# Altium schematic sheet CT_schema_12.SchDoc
size 389 x 385 mm
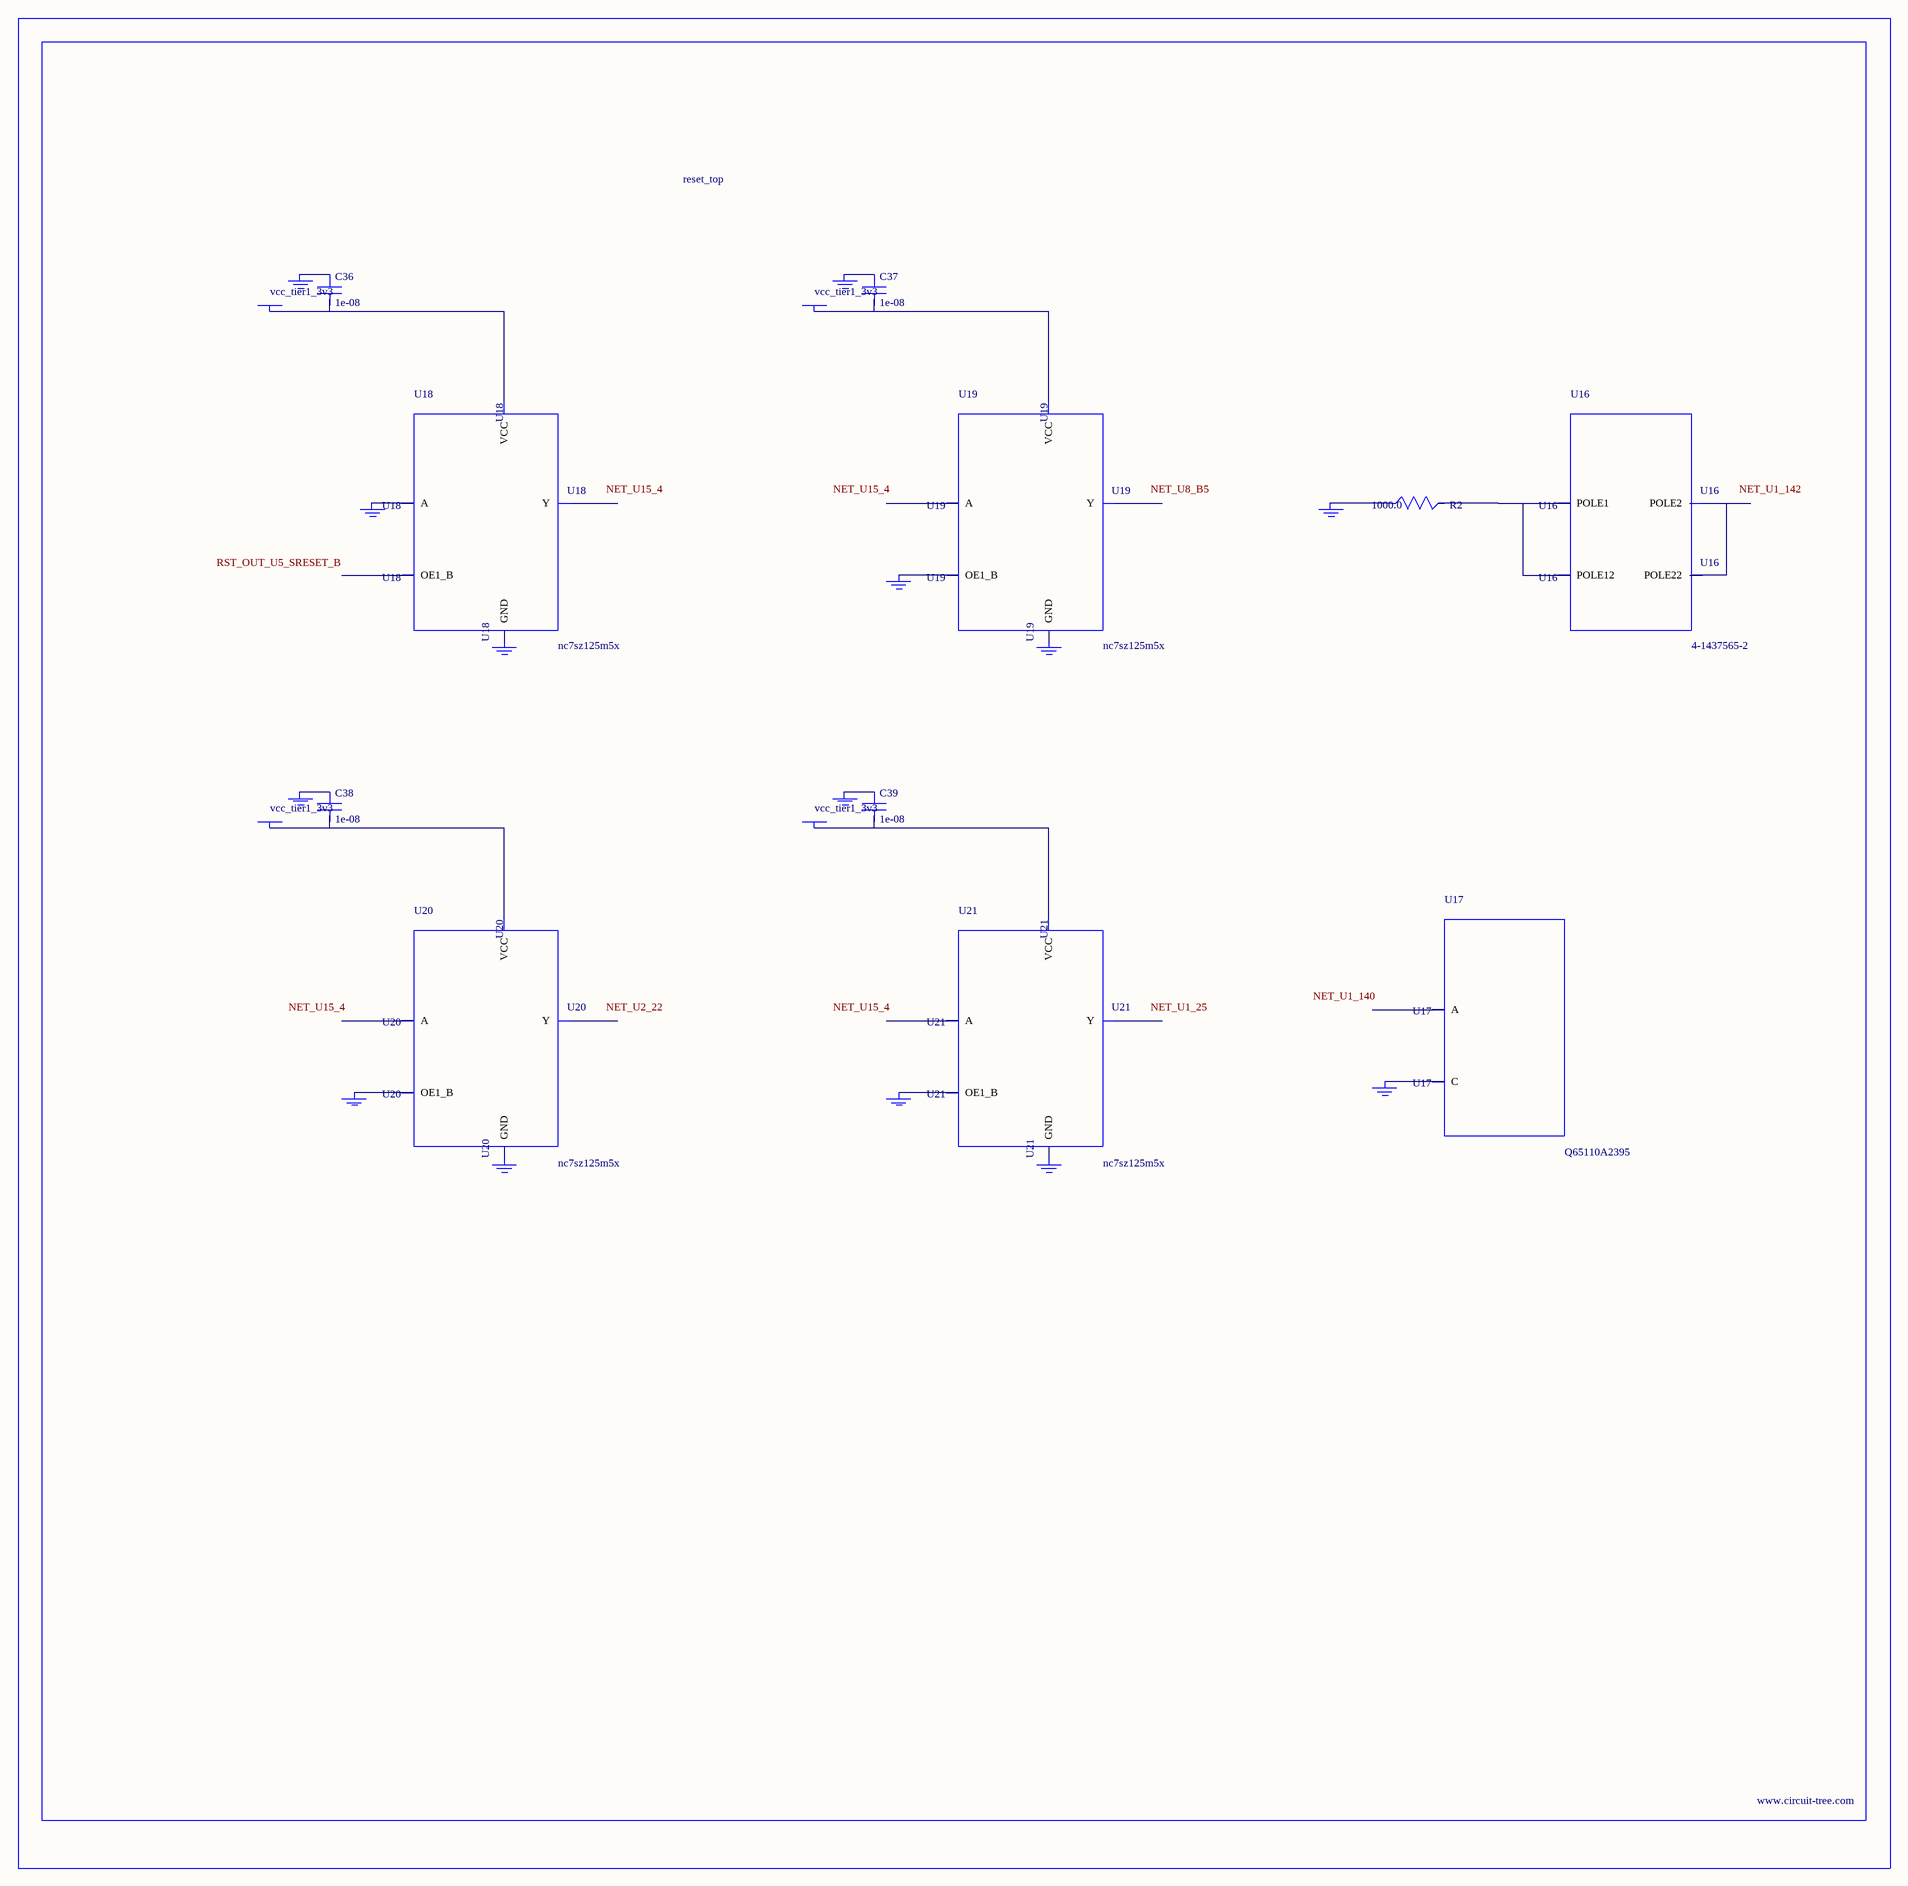
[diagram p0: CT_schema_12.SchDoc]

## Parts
BORDER11  (no value)
C36  1e-08  [C0402]
C37  1e-08  [C0402]
C38  1e-08  [C0402]
C39  1e-08  [C0402]
GND_INSTANCE_11_0  (no value)
GND_INSTANCE_11_1  (no value)
GND_INSTANCE_11_2  (no value)
GND_INSTANCE_11_3  (no value)
GND_INSTANCE_11_4  (no value)
GND_INSTANCE_11_5  (no value)
GND_INSTANCE_11_6  (no value)
GND_INSTANCE_11_7  (no value)
GND_INSTANCE_11_8  (no value)
GND_INSTANCE_11_9  (no value)
GND_INSTANCE_11_10  (no value)
GND_INSTANCE_11_11  (no value)
GND_INSTANCE_11_12  (no value)
GND_INSTANCE_11_13  (no value)
POWER_INSTANCE_11_0  vcc_tier1_3v3
POWER_INSTANCE_11_1  vcc_tier1_3v3
POWER_INSTANCE_11_2  vcc_tier1_3v3
POWER_INSTANCE_11_3  vcc_tier1_3v3
R2  1000.0  [R0603]
U16  4-1437565-2  [SW_4-1437565-2]
U17  Q65110A2395  [LGM67K-G1J2-24-Z]
U18  nc7sz125m5x  [NC7SZ125M5X]
U19  nc7sz125m5x  [NC7SZ125M5X]
U20  nc7sz125m5x  [NC7SZ125M5X]
U21  nc7sz125m5x  [NC7SZ125M5X]

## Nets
NetC36_1: C36.1 GND_INSTANCE_11_2.0(GND)
NetC36_2: C36.2 POWER_INSTANCE_11_0.0(PWR) U18.5(VCC)
NetC37_1: C37.1 GND_INSTANCE_11_5.0(GND)
NetC37_2: C37.2 POWER_INSTANCE_11_1.0(PWR) U19.5(VCC)
NetC38_1: C38.1 GND_INSTANCE_11_8.0(GND)
NetC38_2: C38.2 POWER_INSTANCE_11_2.0(PWR) U20.5(VCC)
NetC39_1: C39.1 GND_INSTANCE_11_11.0(GND)
NetC39_2: C39.2 POWER_INSTANCE_11_3.0(PWR) U21.5(VCC)
NetGND_INSTANCE_11_0_0: GND_INSTANCE_11_0.0(GND) R2.1
NetGND_INSTANCE_11_1_0: GND_INSTANCE_11_1.0(GND) U17.C
NetGND_INSTANCE_11_3_0: GND_INSTANCE_11_3.0(GND) U18.2(A)
NetGND_INSTANCE_11_4_0: GND_INSTANCE_11_4.0(GND) U18.3(GND)
NetGND_INSTANCE_11_6_0: GND_INSTANCE_11_6.0(GND) U19.1(OE1_B)
NetGND_INSTANCE_11_7_0: GND_INSTANCE_11_7.0(GND) U19.3(GND)
NetGND_INSTANCE_11_9_0: GND_INSTANCE_11_9.0(GND) U20.1(OE1_B)
NetGND_INSTANCE_11_10_0: GND_INSTANCE_11_10.0(GND) U20.3(GND)
NetGND_INSTANCE_11_12_0: GND_INSTANCE_11_12.0(GND) U21.1(OE1_B)
NetGND_INSTANCE_11_13_0: GND_INSTANCE_11_13.0(GND) U21.3(GND)
NetR2_2: R2.2 U16.1(POLE1) U16.2(POLE12)
NetU16_3: U16.3(POLE2) U16.4(POLE22)

Not connected (* = marked no-connect by the designer): U17 A; U18 1(OE1_B) 4(Y); U19 2(A) 4(Y); U20 2(A) 4(Y); U21 2(A) 4(Y)

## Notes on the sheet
- Labels drawn without touching a wire or pin: NET_U1_25, NET_U1_140, NET_U1_142, NET_U2_22, NET_U8_B5, NET_U15_4, RST_OUT_U5_SRESET_B

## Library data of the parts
BORDER11 = BORDER_PAGE11
C36-C39 = C0402C103K3RAC
GND_INSTANCE_11_0-GND_INSTANCE_11_13 = GND
POWER_INSTANCE_11_0-POWER_INSTANCE_11_3 = PWR
R2 = RC0603JR-071KL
